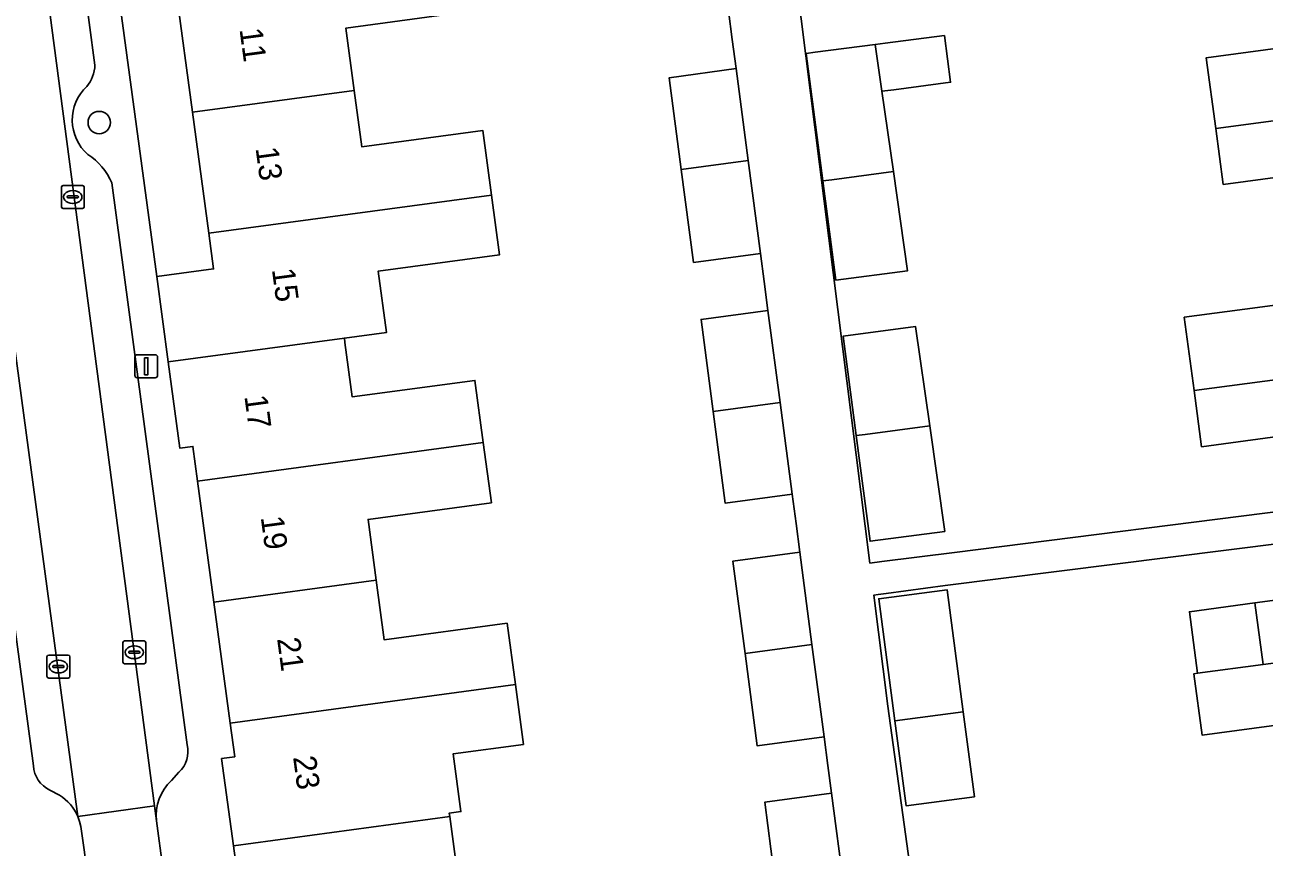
# Model space of a CAD drawing. Extents: x 163147 to 163550, y 380933 to 381639.
# Drawn here: x 163395 to 163449.2, y 381436.9 to 381472.9 of the extents above; entities that cross this region are included whole.
import ezdxf

# ---------------------------------------------------------------- set-up
doc = ezdxf.new("R2010")
doc.units = 0
for name, color, linetype in [('IMGEO_Boom', 7, 'Continuous'), ('IMGEO_Erf', 7, 'Continuous'), ('IMGEO_Kolk', 7, 'Continuous'), ('IMGEO_Lichtmast', 7, 'Continuous'), ('IMGEO_Pand', 7, 'Continuous'), ('IMGEO_Pand_nummerreeks', 7, 'Continuous'), ('IMGEO_Parkeervlak_open', 7, 'Continuous'), ('IMGEO_Rijbaan_lokaal_open', 7, 'Continuous'), ('IMGEO_Voetpad_open', 7, 'Continuous')]:
    doc.layers.add(name, color=color, linetype=linetype)

msp = doc.modelspace()

# ---------------------------------------------------------------- linework, layer by layer
at = {"layer": 'IMGEO_Boom'}
msp.add_circle((163398.233, 381468.643), 0.489, dxfattribs=at)
at = {"layer": 'IMGEO_Erf'}
for points in [[(163396.932, 381490.11), (163400.746, 381461.902), (163403.236, 381462.238), (163403.026, 381463.797), (163402.312, 381469.09), (163401.599, 381474.382), (163400.886, 381479.673), (163400.172, 381484.965), (163399.443, 381490.376)], [(163435.189, 381472.455), (163435.458, 381470.405), (163432.975, 381470.079), (163432.456, 381470.011), (163432.957, 381466.501), (163433.576, 381462.161), (163430.442, 381461.744), (163429.872, 381466.089), (163429.141, 381471.662), (163429.536, 381471.714), (163432.164, 381472.059), (163432.599, 381472.116)], [(163435.204, 381450.754), (163431.941, 381450.327), (163431.334, 381454.949), (163430.764, 381459.297), (163433.925, 381459.718), (163434.545, 381455.376)], [(163436.498, 381439.15), (163433.514, 381438.756), (163433.023, 381442.474), (163432.319, 381447.812), (163435.303, 381448.206), (163436.008, 381442.868)]]:
    msp.add_lwpolyline(points, close=True, dxfattribs=at)
for points in [[(163427.724, 381482.669), (163431.93, 381449.368), (163432.457, 381449.435), (163435.628, 381449.835), (163451.263, 381451.81)], [(163414.281, 381473.481), (163409.01, 381472.77), (163409.377, 381470.045), (163409.709, 381467.585), (163415.005, 381468.299), (163415.386, 381465.469), (163415.738, 381462.859), (163410.437, 381462.145), (163410.799, 381459.461), (163408.952, 381459.211), (163408.977, 381459.025), (163409.298, 381456.638), (163414.659, 381457.361), (163415.025, 381454.645), (163415.38, 381452.01), (163409.986, 381451.283), (163410.345, 381448.623), (163410.697, 381446.011), (163416.068, 381446.735), (163416.429, 381444.058), (163416.783, 381441.435), (163413.705, 381441.021), (163414.045, 381438.503), (163413.538, 381438.434), (163413.559, 381438.282), (163413.943, 381435.435)], [(163427.868, 381434.828), (163427.33, 381438.907), (163430.256, 381439.303), (163430.096, 381440.517), (163429.931, 381441.77), (163427.005, 381441.374), (163426.473, 381445.416), (163425.94, 381449.456), (163428.866, 381449.851), (163428.701, 381451.104), (163428.532, 381452.383), (163425.606, 381451.988), (163425.077, 381456.004), (163424.547, 381460.028), (163427.472, 381460.423), (163427.305, 381461.692), (163427.144, 381462.916), (163424.219, 381462.521), (163423.682, 381466.591), (163423.154, 381470.603), (163426.079, 381470.999), (163425.91, 381472.28), (163425.746, 381473.526)], [(163451.826, 381466.534), (163447.38, 381465.937), (163447.052, 381468.378), (163446.636, 381471.477), (163451.058, 381472.071)], [(163450.814, 381455.047), (163446.435, 381454.459), (163446.105, 381456.915), (163445.674, 381460.121), (163448.878, 381460.552), (163452.562, 381461.048)], [(163452.493, 381450.557), (163435.219, 381448.391), (163432.641, 381448.046), (163432.294, 381447.999), (163432.106, 381447.974), (163432.721, 381443.105), (163438.61, 381400.319), (163441.596, 381377.783), (163442.021, 381377.839), (163445.139, 381378.255), (163461.983, 381380.414)], [(163449.482, 381442.251), (163446.457, 381441.844), (163446.096, 381444.532), (163446.258, 381444.554), (163445.897, 381447.242), (163448.76, 381447.627), (163452.814, 381448.172)]]:
    msp.add_lwpolyline(points, dxfattribs=at)
at = {"layer": 'IMGEO_Kolk'}
for p, q in [((163396.579, 381464.96), (163396.579, 381465.812)), ((163396.654, 381465.886), (163397.506, 381465.886)), ((163397.067, 381465.666), (163397.092, 381465.666)), ((163397.58, 381465.812), (163397.58, 381464.96)), ((163396.838, 381465.38), (163396.838, 381465.392)), ((163397.276, 381465.343), (163396.878, 381465.343)), ((163396.881, 381465.429), (163397.279, 381465.429)), ((163397.09, 381465.106), (163397.065, 381465.106)), ((163397.322, 381465.392), (163397.322, 381465.38)), ((163397.506, 381464.886), (163396.654, 381464.886)), ((163399.267, 381445.043), (163399.267, 381445.895)), ((163399.342, 381445.969), (163400.194, 381445.969)), ((163399.526, 381445.463), (163399.526, 381445.475)), ((163399.569, 381445.512), (163399.967, 381445.512)), ((163399.755, 381445.749), (163399.78, 381445.749)), ((163400.01, 381445.475), (163400.01, 381445.463)), ((163400.268, 381445.895), (163400.268, 381445.043)), ((163395.95, 381444.417), (163395.95, 381445.269)), ((163396.025, 381445.343), (163396.877, 381445.343)), ((163396.438, 381445.123), (163396.463, 381445.123)), ((163396.951, 381445.269), (163396.951, 381444.417)), ((163400.194, 381444.969), (163399.342, 381444.969)), ((163399.964, 381445.426), (163399.566, 381445.426)), ((163399.778, 381445.189), (163399.753, 381445.189)), ((163396.209, 381444.837), (163396.209, 381444.849)), ((163396.647, 381444.8), (163396.249, 381444.8)), ((163396.252, 381444.886), (163396.65, 381444.886)), ((163396.461, 381444.563), (163396.436, 381444.563)), ((163396.693, 381444.849), (163396.693, 381444.837)), ((163396.877, 381444.343), (163396.025, 381444.343))]:
    msp.add_line(p, q, dxfattribs=at)
for points in [[(163396.579, 381464.96), (163396.579, 381465.812)], [(163396.654, 381465.886), (163397.506, 381465.886)], [(163397.58, 381465.812), (163397.58, 381464.96)], [(163397.506, 381464.886), (163396.654, 381464.886)], [(163399.267, 381445.043), (163399.267, 381445.895)], [(163399.342, 381445.969), (163400.194, 381445.969)], [(163400.268, 381445.895), (163400.268, 381445.043)], [(163395.95, 381444.417), (163395.95, 381445.269)], [(163396.025, 381445.343), (163396.877, 381445.343)], [(163396.951, 381445.269), (163396.951, 381444.417)], [(163400.194, 381444.969), (163399.342, 381444.969)], [(163396.877, 381444.343), (163396.025, 381444.343)]]:
    msp.add_lwpolyline(points, dxfattribs=at)
for centre, radius, start, end in [((163396.656, 381465.81), 0.0765, 91.552, 178.448), ((163396.656, 381465.81), 0.0765, 91.552, 178.448), ((163397.504, 381465.81), 0.0765, 1.552, 88.448), ((163397.504, 381465.81), 0.0765, 1.552, 88.448), ((163396.656, 381464.962), 0.0765, 181.552, 268.448), ((163396.656, 381464.962), 0.0765, 181.552, 268.448), ((163396.878, 381465.389), 0.0403, 85.8775, 175.7526), ((163396.875, 381465.379), 0.0366, 178.938, 274.7102), ((163397.279, 381465.386), 0.043, 264.8664, 352.4533), ((163397.283, 381465.391), 0.0386, 1.7309, 96.639), ((163397.504, 381464.962), 0.0765, 271.552, 358.448), ((163397.504, 381464.962), 0.0765, 271.552, 358.448), ((163399.344, 381445.893), 0.0765, 91.552, 178.448), ((163399.344, 381445.893), 0.0765, 91.552, 178.448), ((163399.566, 381445.472), 0.0403, 85.8775, 175.7526), ((163399.563, 381445.462), 0.0366, 178.938, 274.7102), ((163399.967, 381445.469), 0.043, 264.8664, 352.4533), ((163399.971, 381445.474), 0.0386, 1.7309, 96.639), ((163400.192, 381445.893), 0.0765, 1.552, 88.448), ((163400.192, 381445.893), 0.0765, 1.552, 88.448), ((163396.027, 381445.267), 0.0765, 91.552, 178.448), ((163396.027, 381445.267), 0.0765, 91.552, 178.448), ((163396.875, 381445.267), 0.0765, 1.552, 88.448), ((163396.875, 381445.267), 0.0765, 1.552, 88.448), ((163399.344, 381445.045), 0.0765, 181.552, 268.448), ((163399.344, 381445.045), 0.0765, 181.552, 268.448), ((163400.192, 381445.045), 0.0765, 271.552, 358.448), ((163400.192, 381445.045), 0.0765, 271.552, 358.448), ((163396.027, 381444.419), 0.0765, 181.552, 268.448), ((163396.027, 381444.419), 0.0765, 181.552, 268.448), ((163396.249, 381444.846), 0.0403, 85.8775, 175.7526), ((163396.246, 381444.836), 0.0366, 178.938, 274.7102), ((163396.65, 381444.843), 0.043, 264.8664, 352.4533), ((163396.654, 381444.848), 0.0386, 1.7309, 96.639), ((163396.875, 381444.419), 0.0765, 271.552, 358.448), ((163396.875, 381444.419), 0.0765, 271.552, 358.448)]:
    msp.add_arc(centre, radius, start, end, dxfattribs=at)
for centre, major_axis, ratio, start_param, end_param in [((163397.066, 381465.386), (-0.387, 0.002), 0.722429, 4.712389, 7.853982), ((163397.091, 381465.386), (-0.39, 0.002), 0.717154, 1.570796, 4.712389), ((163399.754, 381445.469), (-0.387, 0.002), 0.722429, 4.712389, 7.853982), ((163399.779, 381445.469), (-0.39, 0.002), 0.717154, 1.570796, 4.712389), ((163396.437, 381444.843), (-0.387, 0.002), 0.722429, 4.712389, 7.853982), ((163396.462, 381444.843), (-0.39, 0.002), 0.717154, 1.570796, 4.712389)]:
    msp.add_ellipse(centre, major_axis=major_axis, ratio=ratio, start_param=start_param, end_param=end_param, dxfattribs=at)
at = {"layer": 'IMGEO_Lichtmast'}
for p, q in [((163399.895, 381458.481), (163400.685, 381458.481)), ((163400.685, 381458.481), (163399.895, 381458.481)), ((163399.795, 381457.581), (163399.795, 381458.381)), ((163399.795, 381458.381), (163399.795, 381457.581)), ((163400.785, 381458.381), (163400.785, 381457.581)), ((163400.785, 381457.581), (163400.785, 381458.381)), ((163400.685, 381457.481), (163399.895, 381457.481)), ((163399.895, 381457.481), (163400.685, 381457.481))]:
    msp.add_line(p, q, dxfattribs=at)
msp.add_lwpolyline([(163400.215, 381458.356), (163400.365, 381458.356), (163400.365, 381457.606), (163400.215, 381457.606), (163400.215, 381458.356)], dxfattribs=at)
for centre, start, end in [((163399.895, 381458.381), 90, 180), ((163399.895, 381458.381), 90, 180), ((163400.685, 381458.381), 0, 90), ((163400.685, 381458.381), 360, 90), ((163399.895, 381457.581), 180, 270), ((163399.895, 381457.581), 180, 270), ((163400.685, 381457.581), 270, 0), ((163400.685, 381457.581), 270, 0)]:
    msp.add_arc(centre, 0.1, start, end, dxfattribs=at)
at = {"layer": 'IMGEO_Pand'}
for points in [[(163401.599, 381474.382), (163402.312, 381469.09), (163409.377, 381470.045), (163409.01, 381472.77), (163414.281, 381473.481), (163413.935, 381476.049)], [(163458.946, 381475.41), (163458.917, 381475.626), (163450.727, 381474.536), (163451.058, 381472.071), (163446.636, 381471.477), (163447.052, 381468.378), (163459.658, 381470.057)], [(163432.456, 381470.011), (163432.164, 381472.059), (163429.536, 381471.714), (163429.141, 381471.662), (163429.872, 381466.089), (163430.267, 381466.142), (163432.957, 381466.501)], [(163435.189, 381472.455), (163432.599, 381472.116), (163432.164, 381472.059), (163432.456, 381470.011), (163432.975, 381470.079), (163435.458, 381470.405)], [(163426.079, 381470.999), (163423.154, 381470.603), (163423.682, 381466.591), (163426.608, 381466.987)], [(163403.026, 381463.797), (163415.386, 381465.469), (163415.005, 381468.299), (163409.709, 381467.585), (163409.377, 381470.045), (163402.312, 381469.09)], [(163459.658, 381470.057), (163447.052, 381468.378), (163447.38, 381465.937), (163451.826, 381466.534), (163452.196, 381463.777), (163452.246, 381463.402), (163460.96, 381464.562), (163460.941, 381464.708), (163460.38, 381464.634)], [(163426.608, 381466.987), (163423.682, 381466.591), (163424.219, 381462.521), (163427.144, 381462.916)], [(163432.957, 381466.501), (163430.267, 381466.142), (163429.872, 381466.089), (163430.442, 381461.744), (163433.576, 381462.161)], [(163410.437, 381462.145), (163415.738, 381462.859), (163415.386, 381465.469), (163403.026, 381463.797), (163403.236, 381462.238), (163400.746, 381461.902), (163401.249, 381458.17), (163408.952, 381459.211), (163410.799, 381459.461)], [(163460.96, 381464.562), (163452.246, 381463.402), (163452.562, 381461.048), (163448.878, 381460.552), (163445.674, 381460.121), (163446.105, 381456.915), (163458.68, 381458.589), (163461.702, 381458.991)], [(163427.472, 381460.423), (163424.547, 381460.028), (163425.077, 381456.004), (163428.003, 381456.399)], [(163431.334, 381454.949), (163431.727, 381455.001), (163434.545, 381455.376), (163433.925, 381459.718), (163430.764, 381459.297)], [(163408.977, 381459.025), (163408.952, 381459.211), (163401.249, 381458.17), (163401.757, 381454.399), (163402.332, 381454.476), (163402.537, 381452.957), (163415.025, 381454.645), (163414.659, 381457.361), (163409.298, 381456.638)], [(163458.7, 381458.437), (163458.68, 381458.589), (163446.105, 381456.915), (163446.435, 381454.459), (163450.814, 381455.047), (163451.263, 381451.81), (163454.481, 381452.238), (163459.437, 381452.898)], [(163428.003, 381456.399), (163425.077, 381456.004), (163425.606, 381451.988), (163428.532, 381452.383)], [(163434.545, 381455.376), (163431.727, 381455.001), (163431.334, 381454.949), (163431.941, 381450.327), (163435.204, 381450.754)], [(163410.345, 381448.623), (163409.986, 381451.283), (163415.38, 381452.01), (163415.025, 381454.645), (163402.537, 381452.957), (163403.25, 381447.664)], [(163460.315, 381446.402), (163459.628, 381451.515), (163454.673, 381450.85), (163452.493, 381450.557), (163452.814, 381448.172), (163448.76, 381447.627), (163449.121, 381444.939)], [(163428.866, 381449.851), (163425.94, 381449.456), (163426.473, 381445.416), (163429.398, 381445.812)], [(163410.345, 381448.623), (163403.25, 381447.664), (163403.964, 381442.372), (163416.429, 381444.058), (163416.068, 381446.735), (163410.697, 381446.011)], [(163435.303, 381448.206), (163432.319, 381447.812), (163433.023, 381442.474), (163436.008, 381442.868)], [(163448.76, 381447.627), (163445.897, 381447.242), (163446.258, 381444.554), (163449.121, 381444.939)], [(163460.315, 381446.402), (163449.121, 381444.939), (163446.258, 381444.554), (163446.096, 381444.532), (163446.457, 381441.844), (163449.482, 381442.251), (163453.535, 381442.796), (163453.85, 381440.45), (163460.986, 381441.408)], [(163429.398, 381445.812), (163426.473, 381445.416), (163427.005, 381441.374), (163429.931, 381441.77)], [(163416.783, 381441.435), (163416.429, 381444.058), (163403.964, 381442.372), (163404.163, 381440.896), (163403.587, 381440.818), (163404.101, 381437.004), (163413.559, 381438.282), (163413.538, 381438.434), (163414.045, 381438.503), (163413.705, 381441.021)], [(163436.008, 381442.868), (163433.023, 381442.474), (163433.514, 381438.756), (163436.498, 381439.15)], [(163430.256, 381439.303), (163427.33, 381438.907), (163427.868, 381434.828), (163430.793, 381435.224)], [(163419.568, 381433.706), (163419.239, 381436.149), (163413.943, 381435.435), (163413.559, 381438.282), (163404.101, 381437.004), (163404.594, 381433.348), (163407.029, 381433.676), (163407.249, 381432.04)]]:
    msp.add_lwpolyline(points, close=True, dxfattribs=at)
at = {"layer": 'IMGEO_Parkeervlak_open'}
for points in [[(163397.305, 381438.279), (163390.624, 381487.807), (163390.542, 381488.417)], [(163394.076, 381488.632), (163394.123, 381488.276), (163400.646, 381438.752), (163400.732, 381438.101)], [(163389.334, 381485.315), (163395.359, 381440.505)], [(163398.046, 381471.158), (163397.296, 381476.773)], [(163402.08, 381441.416), (163398.785, 381465.999)], [(163401.388, 381439.857), (163401.72, 381440.224)], [(163396.078, 381439.436), (163396.496, 381439.218)]]:
    msp.add_lwpolyline(points, dxfattribs=at)
for centre, radius, start, end in [((163396.511, 381471.209), 1.535, 319.9062, 358.1007), ((163399.056, 381468.757), 2.004, 133.1193, 228.8469), ((163396.205, 381464.898), 2.805, 23.1058, 56.8923), ((163400.891, 381441.125), 1.224, 312.6147, 13.7753), ((163396.607, 381440.568), 1.25, 182.9057, 244.9432), ((163402.869, 381438.303), 2.146, 133.6213, 185.4097), ((163395.417, 381437.47), 2.054, 23.1858, 58.3076)]:
    msp.add_arc(centre, radius, start, end, dxfattribs=at)
at = {"layer": 'IMGEO_Rijbaan_lokaal_open'}
for points in [[(163397.305, 381438.279), (163400.646, 381438.752), (163394.123, 381488.276), (163390.624, 381487.807)], [(163400.646, 381438.752), (163397.305, 381438.279), (163397.368, 381438.071), (163397.436, 381437.845), (163397.745, 381435.583), (163397.862, 381434.723), (163397.929, 381434.214), (163401.189, 381434.693), (163401.01, 381436.026), (163400.732, 381438.101)]]:
    msp.add_lwpolyline(points, close=True, dxfattribs=at)
at = {"layer": 'IMGEO_Voetpad_open'}
for points in [[(163405.797, 381424.407), (163405.542, 381426.303), (163404.594, 381433.348), (163404.101, 381437.004), (163403.587, 381440.818), (163404.163, 381440.896), (163403.964, 381442.372), (163403.25, 381447.664), (163402.537, 381452.957), (163402.332, 381454.476), (163401.757, 381454.399), (163401.249, 381458.17), (163400.746, 381461.902), (163396.932, 381490.11), (163393.804, 381490.754), (163394.076, 381488.632)], [(163395.359, 381440.505), (163389.334, 381485.315)], [(163451.263, 381451.81), (163435.628, 381449.835), (163432.457, 381449.435), (163431.93, 381449.368), (163427.724, 381482.669)], [(163397.296, 381476.773), (163398.046, 381471.158)], [(163425.746, 381473.526), (163425.91, 381472.28), (163426.079, 381470.999), (163426.608, 381466.987), (163427.144, 381462.916), (163427.305, 381461.692), (163427.472, 381460.423), (163428.003, 381456.399), (163428.532, 381452.383), (163428.701, 381451.104), (163428.866, 381449.851), (163429.398, 381445.812), (163429.931, 381441.77), (163430.096, 381440.517), (163430.256, 381439.303), (163430.793, 381435.224)], [(163398.785, 381465.999), (163402.08, 381441.416)], [(163461.983, 381380.414), (163445.139, 381378.255), (163442.021, 381377.839), (163441.596, 381377.783), (163438.61, 381400.319), (163432.721, 381443.105), (163432.106, 381447.974), (163432.294, 381447.999), (163432.641, 381448.046), (163435.219, 381448.391), (163452.493, 381450.557)], [(163401.72, 381440.224), (163401.388, 381439.857)], [(163396.496, 381439.218), (163396.078, 381439.436)], [(163397.862, 381434.723), (163397.745, 381435.583), (163397.436, 381437.845), (163397.368, 381438.071), (163397.305, 381438.279)], [(163400.732, 381438.101), (163401.01, 381436.026), (163401.189, 381434.693), (163401.335, 381433.603)]]:
    msp.add_lwpolyline(points, dxfattribs=at)
for centre, radius, start, end in [((163396.511, 381471.209), 1.535, 319.9062, 358.1007), ((163399.056, 381468.757), 2.004, 133.1193, 228.8469), ((163396.205, 381464.898), 2.805, 23.1058, 56.8923), ((163400.891, 381441.125), 1.224, 312.6147, 13.7753), ((163396.607, 381440.568), 1.25, 182.9057, 244.9432), ((163402.869, 381438.303), 2.146, 133.6213, 185.4097), ((163395.417, 381437.47), 2.054, 23.1858, 58.3076)]:
    msp.add_arc(centre, radius, start, end, dxfattribs=at)

# ---------------------------------------------------------------- texts
at = {"layer": 'IMGEO_Pand_nummerreeks'}
for s, rotation, p in [('11', 277.6772, (163404.365, 381472.723)), ('13', 277.6772, (163405.067, 381467.521)), ('15', 277.6774, (163405.781, 381462.218)), ('17', 277.6774, (163404.579, 381456.668)), ('19', 277.6789, (163405.293, 381451.376)), ('21', 277.6789, (163406.009, 381446.062)), ('23', 277.6774, (163406.708, 381440.883))]:
    msp.add_text(s, height=1, rotation=rotation, dxfattribs=at).set_placement(p)

doc.saveas('drawing.dxf')
